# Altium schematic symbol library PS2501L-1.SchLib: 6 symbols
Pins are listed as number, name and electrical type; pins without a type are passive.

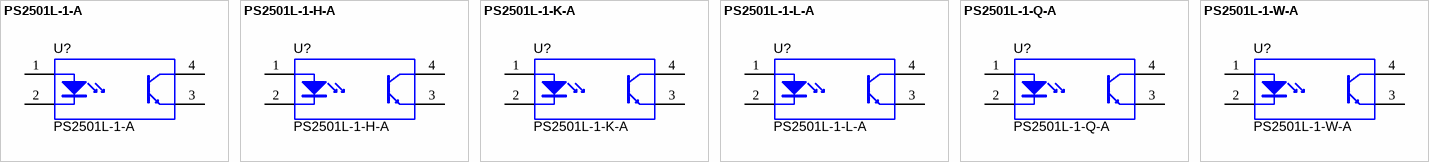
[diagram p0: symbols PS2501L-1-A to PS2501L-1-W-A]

## PS2501L-1-A
designator U?
High Isolation Voltage Single Transistor Type OptoCoupler 80-600% CTR; Manufacturer: California Eastern Laboratories; U/M: EA
footprint PS2501L
pins: 1 A, 2 K, 3 E, 4 C

## PS2501L-1-H-A
designator U?
High Isolation Voltage Single Transistor Type OptoCoupler 80-160% CTR; Manufacturer: California Eastern Laboratories; U/M: EA; Current Transfer Ratio (Min): 80% @ 5mA; Current Transfer Ratio (Max): 160% @ 5mA
footprint PS2501L
pins: 1 A, 2 K, 3 E, 4 C

## PS2501L-1-K-A
designator U?
High Isolation Voltage Single Transistor Type OptoCoupler 300-600% CTR; Manufacturer: California Eastern Laboratories; U/M: EA; Current Transfer Ratio (Min): 300% @ 5mA; Current Transfer Ratio (Max): 600% @ 5mA
footprint PS2501L
pins: 1 A, 2 K, 3 E, 4 C

## PS2501L-1-L-A
designator U?
High Isolation Voltage Single Transistor Type OptoCoupler 200-400% CTR; Manufacturer: California Eastern Laboratories; U/M: EA; Current Transfer Ratio (Min): 200% @ 5mA; Current Transfer Ratio (Max): 400% @ 5mA
footprint PS2501L
pins: 1 A, 2 K, 3 E, 4 C

## PS2501L-1-Q-A
designator U?
High Isolation Voltage Single Transistor Type OptoCoupler 100-200% CTR; Manufacturer: California Eastern Laboratories; U/M: EA; Current Transfer Ratio (Min): 100% @ 5mA; Current Transfer Ratio (Max): 200% @ 5mA
footprint PS2501L
pins: 1 A, 2 K, 3 E, 4 C

## PS2501L-1-W-A
designator U?
High Isolation Voltage Single Transistor Type OptoCoupler 130-260%; Manufacturer: California Eastern Laboratories; U/M: EA; Current Transfer Ratio (Min): 130% @ 5mA; Current Transfer Ratio (Max): 260% @ 5mA
footprint PS2501L
pins: 1 A, 2 K, 3 E, 4 C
